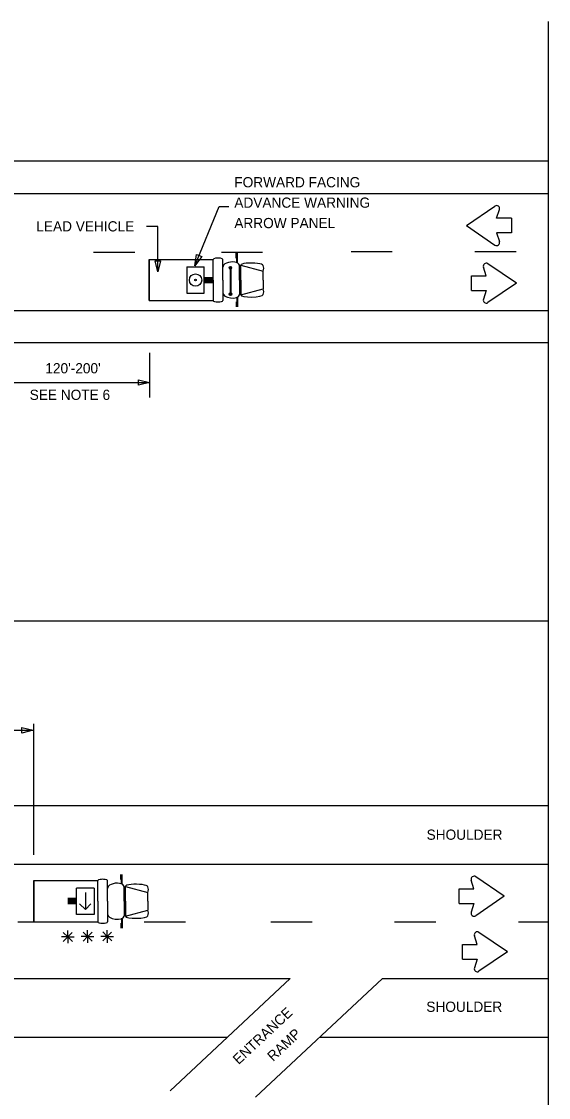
# Model space of a CAD drawing. Extents: x -747 to 834, y -5485 to -3577.
# Drawn here: x -256 to 53, y -5074 to -4442 of the extents above; entities that cross this region are included whole.
import ezdxf

# ---------------------------------------------------------------- set-up
doc = ezdxf.new("R2010")
doc.units = 0
doc.layers.add('Working Level 1', color=7, linetype='Continuous')

msp = doc.modelspace()

# ---------------------------------------------------------------- linework, layer by layer
at = {"layer": 'Working Level 1'}
for p, q in [((52.99, -4442.19), (52.99, -5484.51)), ((-746.8, -4524.13), (52.95, -4524.13)), ((-746.8, -4543.26), (52.95, -4543.26)), ((5.09, -4562.09), (21.76, -4550.65)), ((22.81, -4557.72), (24.44, -4552.65)), ((31.49, -4557.72), (22.81, -4557.72)), ((31.49, -4557.72), (31.49, -4566.45)), ((5.09, -4562.09), (21.76, -4573.52)), ((31.49, -4566.45), (22.81, -4566.45)), ((22.81, -4566.45), (24.44, -4571.53)), ((-181.3, -4581.96), (-143.75, -4581.96)), ((-181.3, -4606.22), (-181.3, -4581.96)), ((-181.3, -4581.96), (-181.3, -4606.21)), ((-143.75, -4594.09), (-143.75, -4581.96)), ((-138, -4594.09), (-138, -4581.96)), ((-130.24, -4581.23), (-130.24, -4578.27)), ((-129.77, -4584.09), (-129.77, -4578.27)), ((-129.38, -4584.09), (-129.38, -4578.27)), ((-159.24, -4586.32), (-148.98, -4586.32)), ((-159.24, -4586.32), (-159.24, -4601.85)), ((-148.98, -4601.85), (-148.98, -4586.32)), ((-134.33, -4586.71), (-134.33, -4586.71)), ((-133.71, -4587.06), (-133.71, -4602.12)), ((-133.67, -4587.06), (-133.67, -4602.12)), ((-133.63, -4587.06), (-133.63, -4602.12)), ((-133.55, -4587.06), (-133.55, -4602.12)), ((-133.45, -4586.21), (-133.45, -4586.21)), ((-133.43, -4587.06), (-133.43, -4602.12)), ((-128.36, -4594.09), (-128.36, -4585.35)), ((-127.56, -4585.35), (-114.43, -4588.94)), ((-127.56, -4594.09), (-127.56, -4585.35)), ((-114.43, -4594.09), (-114.43, -4588.94)), ((16.66, -4591.58), (15.03, -4586.51)), ((34.38, -4595.95), (17.71, -4584.51)), ((-148.98, -4592.53), (-143.75, -4592.53)), ((-148.98, -4593.31), (-143.75, -4593.31)), ((-148.98, -4594.09), (-143.75, -4594.09)), ((-148.98, -4594.86), (-143.75, -4594.86)), ((-148.98, -4595.64), (-143.75, -4595.64)), ((-143.75, -4594.09), (-143.75, -4606.21)), ((-138, -4594.09), (-138, -4606.21)), ((-128.36, -4594.09), (-128.36, -4602.82)), ((-127.56, -4594.09), (-127.56, -4602.82)), ((-114.43, -4594.09), (-114.43, -4599.23)), ((7.98, -4600.31), (7.98, -4591.58)), ((7.98, -4591.58), (16.66, -4591.58)), ((34.38, -4595.95), (17.71, -4607.38)), ((-159.24, -4601.85), (-148.98, -4601.85)), ((-134.29, -4602.25), (-134.29, -4602.25)), ((-133.41, -4601.74), (-133.41, -4601.74)), ((-127.56, -4602.82), (-114.43, -4599.23)), ((7.98, -4600.31), (16.66, -4600.31)), ((16.66, -4600.31), (15.03, -4605.38)), ((-181.3, -4606.21), (-143.75, -4606.21)), ((-130.24, -4606.94), (-130.24, -4609.91)), ((-129.77, -4604.08), (-129.77, -4609.91)), ((-129.38, -4604.08), (-129.38, -4609.91)), ((-746.8, -4611.95), (52.95, -4611.95)), ((-746.8, -4630.83), (52.95, -4630.83)), ((-181.13, -4636.89), (-181.13, -4663.07)), ((-264.43, -4654.36), (-181.13, -4654.36)), ((-746.8, -4794.34), (53.25, -4794.34)), ((-249.31, -4854.96), (-249.31, -4931.85)), ((-313.45, -4858.66), (-249.31, -4858.66)), ((-746.8, -4902.87), (53.25, -4902.87)), ((-455.82, -4937.35), (53.25, -4937.35)), ((-197.99, -4946.33), (-197.99, -4943.36)), ((-197.52, -4949.18), (-197.52, -4943.36)), ((-197.12, -4949.18), (-197.12, -4943.36)), ((-249.04, -4947.05), (-211.49, -4947.05)), ((-249.04, -4971.31), (-249.04, -4947.05)), ((-249.04, -4947.05), (-249.04, -4971.3)), ((-211.49, -4959.18), (-211.49, -4947.05)), ((-205.74, -4959.18), (-205.74, -4947.05)), ((-196.11, -4959.18), (-196.11, -4950.44)), ((-195.3, -4950.44), (-182.18, -4954.03)), ((-195.3, -4959.18), (-195.3, -4950.44)), ((9.48, -4951.82), (7.85, -4946.75)), ((27.2, -4956.19), (10.53, -4944.75)), ((-213.7, -4951.42), (-223.96, -4951.42)), ((-223.96, -4966.94), (-223.96, -4951.42)), ((-218.83, -4954.05), (-218.83, -4963.98)), ((-213.7, -4951.42), (-213.7, -4966.94)), ((-182.18, -4959.18), (-182.18, -4954.03)), ((0.81, -4960.55), (0.81, -4951.82)), ((0.81, -4951.82), (9.48, -4951.82)), ((27.2, -4956.19), (10.53, -4967.63)), ((-223.96, -4957.63), (-229.19, -4957.63)), ((-223.96, -4958.41), (-229.19, -4958.41)), ((-223.96, -4959.18), (-229.19, -4959.18)), ((-223.96, -4959.96), (-229.19, -4959.96)), ((-223.96, -4960.73), (-229.19, -4960.73)), ((-218.83, -4963.98), (-222.2, -4960.61)), ((-218.83, -4963.98), (-215.53, -4960.69)), ((-211.49, -4959.18), (-211.49, -4971.3)), ((-205.74, -4959.18), (-205.74, -4971.3)), ((-196.11, -4959.18), (-196.11, -4967.91)), ((-195.3, -4959.18), (-195.3, -4967.91)), ((-182.18, -4959.18), (-182.18, -4964.32)), ((0.81, -4960.55), (9.48, -4960.55)), ((9.48, -4960.55), (7.85, -4965.63)), ((-213.7, -4966.94), (-223.96, -4966.94)), ((-197.52, -4969.17), (-197.52, -4975)), ((-197.12, -4969.17), (-197.12, -4975)), ((-195.3, -4967.91), (-182.18, -4964.32)), ((-249.04, -4971.3), (-211.49, -4971.3)), ((-197.99, -4972.03), (-197.99, -4975)), ((35.61, -4971.34), (53.25, -4971.34)), ((-229.13, -4980.09), (-232.89, -4980.09)), ((-229.13, -4980.09), (-231.79, -4977.43)), ((-229.13, -4980.09), (-231.79, -4982.75)), ((-229.19, -4980.14), (-226.53, -4977.48)), ((-229.13, -4980.09), (-229.13, -4976.33)), ((-229.13, -4980.09), (-226.47, -4982.75)), ((-229.13, -4980.09), (-229.13, -4983.85)), ((-229.13, -4980.09), (-225.37, -4980.09)), ((-217.51, -4979.93), (-221.28, -4979.93)), ((-217.51, -4979.93), (-220.17, -4977.27)), ((-217.51, -4979.93), (-220.17, -4982.59)), ((-217.58, -4979.98), (-214.91, -4977.32)), ((-217.51, -4979.93), (-217.51, -4976.17)), ((-217.51, -4979.93), (-214.85, -4982.59)), ((-217.51, -4979.93), (-217.51, -4983.69)), ((-217.51, -4979.93), (-213.75, -4979.93)), ((-205.98, -4979.85), (-209.74, -4979.85)), ((-205.98, -4979.85), (-208.64, -4977.19)), ((-205.98, -4979.85), (-208.64, -4982.51)), ((-206.04, -4979.9), (-203.38, -4977.24)), ((-205.98, -4979.85), (-205.98, -4976.09)), ((-205.98, -4979.85), (-203.32, -4982.51)), ((-205.98, -4979.85), (-205.98, -4983.61)), ((-205.98, -4979.85), (-202.22, -4979.85)), ((11.37, -4984.51), (9.74, -4979.44)), ((29.09, -4988.87), (12.42, -4977.44)), ((2.69, -4993.24), (2.69, -4984.51)), ((2.69, -4984.51), (11.37, -4984.51)), ((2.69, -4993.24), (11.37, -4993.24)), ((11.37, -4993.24), (9.74, -4998.31)), ((29.09, -4988.87), (12.42, -5000.31)), ((-746.8, -5004.57), (-98.45, -5004.57)), ((-98.45, -5004.57), (-168.98, -5070.52)), ((-44.33, -5004.57), (-118.81, -5074.22)), ((-44.33, -5004.57), (53.25, -5004.57)), ((-746.8, -5039.06), (-135.33, -5039.06)), ((-81.21, -5039.06), (53.25, -5039.06))]:
    msp.add_line(p, q, dxfattribs=at)
for points in [[(-154.41, -4585.7), (-140.27, -4550.92), (-134.5, -4550.92)], [(-176.22, -4589.25), (-176.22, -4562.55), (-182.84, -4562.55)], [(-62.75, -4577.38), (-38.5, -4577.38)], [(10, -4577.38), (34.26, -4577.38)], [(-214.04, -4577.71), (-189.79, -4577.71)], [(-138.91, -4577.71), (-114.66, -4577.71)], [(-134.35, -4586.98), (-134.09, -4587.43)], [(-134.33, -4586.71), (-133.85, -4587.56)], [(-134.27, -4586.53), (-133.66, -4587.6)], [(-134.18, -4586.4), (-133.5, -4587.58)], [(-134.07, -4586.3), (-133.35, -4587.54)], [(-133.95, -4586.21), (-133.23, -4587.47)], [(-133.81, -4586.17), (-133.12, -4587.37)], [(-133.66, -4586.14), (-133.02, -4587.25)], [(-133.47, -4586.16), (-132.95, -4587.08)], [(-133.26, -4586.24), (-132.91, -4586.85)], [(-134.31, -4602.51), (-134.04, -4602.97)], [(-134.29, -4602.25), (-133.8, -4603.09)], [(-134.23, -4602.06), (-133.62, -4603.13)], [(-134.14, -4601.93), (-133.46, -4603.11)], [(-134.03, -4601.83), (-133.31, -4603.07)], [(-133.91, -4601.75), (-133.18, -4603)], [(-133.77, -4601.71), (-133.07, -4602.91)], [(-133.62, -4601.67), (-132.98, -4602.78)], [(-133.43, -4601.69), (-132.9, -4602.62)], [(-133.22, -4601.77), (-132.87, -4602.39)], [(-258.42, -4971.34), (-234.16, -4971.34)], [(-184.34, -4971.34), (-160.08, -4971.34)], [(-109.9, -4971.34), (-85.64, -4971.34)], [(-37.14, -4971.34), (-12.89, -4971.34)]]:
    msp.add_lwpolyline(points, dxfattribs=at)
for points in [[(-174.59, -4582.75), (-176.22, -4589.25), (-177.84, -4582.75)], [(-150.46, -4580.29), (-154.41, -4585.7), (-153.47, -4579.07)], [(-187.63, -4652.73), (-181.13, -4654.36), (-187.63, -4655.98)], [(-256.08, -4857.04), (-249.58, -4858.66), (-256.08, -4860.29)]]:
    msp.add_lwpolyline(points, close=True, dxfattribs=at)
for centre, radius in [((-133.63, -4586.87), 0.728), ((-154.11, -4594.09), 3.62), ((-154.11, -4594.09), 0.451), ((-133.59, -4602.4), 0.728)]:
    msp.add_circle(centre, radius, dxfattribs=at)
for centre, radius, start, end in [((22.76, -4552.11), 1.77, 342.18241, 124.44548), ((22.76, -4572.07), 1.77, 235.55454, 17.81761), ((-117.64, -4587.22), 3.64, 331.88006, 28.11991), ((16.71, -4585.97), 1.77, 55.55454, 197.81761), ((-117.64, -4600.95), 3.64, 331.88008, 28.11994), ((16.71, -4605.92), 1.77, 162.1824, 304.44547), ((-185.39, -4952.31), 3.64, 331.88006, 28.11991), ((9.54, -4946.21), 1.77, 55.55454, 197.81761), ((-185.39, -4966.04), 3.64, 331.88008, 28.11994), ((9.54, -4966.17), 1.77, 162.1824, 304.44547), ((11.42, -4978.9), 1.77, 55.55454, 197.81761), ((11.42, -4998.85), 1.77, 162.1824, 304.44547)]:
    msp.add_arc(centre, radius, start, end, dxfattribs=at)
for centre, major_axis, ratio, start_param, end_param in [((-140.87, -4581.96), (2.88, 0), 0.269913, 0, 3.141593), ((-133.18, -4585.95), (4.82, 0.6), 0.503092, 0, 3.141593), ((-121, -4585.43), (6.56, -0.08), 0.2034, 0, 3.141593), ((-133.18, -4602.22), (4.82, -0.6), 0.503092, 3.141593, 6.283185), ((-121, -4602.75), (6.56, 0.08), 0.2034, 3.141593, 6.283185), ((-140.87, -4606.21), (2.88, 0), 0.269913, 3.141593, 6.283185), ((-208.62, -4947.05), (2.88, 0), 0.269913, 0, 3.141593), ((-200.92, -4951.04), (4.82, 0.6), 0.503092, 0, 3.141593), ((-188.74, -4950.52), (6.56, -0.08), 0.2034, 0, 3.141593), ((-200.92, -4967.31), (4.82, -0.6), 0.503092, 3.141593, 6.283185), ((-188.74, -4967.84), (6.56, 0.08), 0.2034, 3.141593, 6.283185), ((-208.62, -4971.3), (2.88, 0), 0.269913, 3.141593, 6.283185)]:
    msp.add_ellipse(centre, major_axis=major_axis, ratio=ratio, start_param=start_param, end_param=end_param, dxfattribs=at)

# ---------------------------------------------------------------- texts
for s, p in [('FORWARD FACING', (-131.31, -4539.62)), ('ADVANCE WARNING ', (-131.31, -4551.62)), ('ARROW PANEL', (-131.31, -4563.62)), ('LEAD VEHICLE', (-247.64, -4565.55)), ("120'-200'", (-242.34, -4648.94)), ('SEE NOTE 6', (-251.53, -4664.55))]:
    msp.add_text(s, height=6, dxfattribs=at).set_placement(p)
for s, rotation, p in [('SHOULDER', 0, (-18.34, -4923.03)), ('SHOULDER', 0, (-18.5, -5024.15)), ('ENTRANCE', 43.07908, (-128.79, -5055.47)), ('RAMP', 43.07908, (-108.54, -5053.62))]:
    msp.add_text(s, height=6, rotation=rotation, dxfattribs=at).set_placement(p)

doc.saveas('drawing.dxf')
